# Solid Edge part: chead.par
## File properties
Title: Cross Head
Subject: Carrier Assembly
Author: kiyo
Keywords: Block
Comments: Cross Head
Template: metric.par
Last saved by: edge
Revision: 36
Application: Solid Edge
File Size: 0
Number of Sheets: 0
Number of Objects: 0
Username: kiyo
文書内容のタイプ: 0
Material: チタン, 純金属
Face Style: Steel
Fill Style: ANSI31(Iron)
Virtual Style: 銀
Coef. of Thermal Exp: 0.0
Thermal Conductivity: 16.0
Specific Heat: 519.0
Modulus of Elasticity: 102731879300.0
Poisson's Ratio: 0.34
Yield Stress: 172368925.0
Ultimate Stress: 241316495.0
Elongation: 0.0
Category: Machined Block
Manager: Brian Little
Company: Wheels R Us
Density: 7702
Accuracy: 0.00
Document Number: C-3701
Revision: 1
Project Name: Trolley Wheel Assembly
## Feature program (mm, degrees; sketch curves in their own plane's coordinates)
sketch for "unnamed Protrusion 1" plane through (0, 0, 0) normal (0, -1, 0) x-axis (1, 0, 0)
  line (-53.3125, 21.0114) -> (66.6875, 21.0114)
  line (66.6875, 21.0114) -> (66.6875, -28.9886)
  line (66.6875, -28.9886) -> (-53.3125, -28.9886)
  line (-53.3125, -28.9886) -> (-53.3125, 21.0114)
extrude "unnamed Protrusion 1" add finite 140 along -normal
sketch for "unnamed Hole 1" plane through (6.6875, 0, -3.9886) normal (0, -1, 0) x-axis (1, 0, 0)
  hole centre (30, 0) bore radius 10
hole "unnamed Hole 1" through
sketch for "Hole_2" plane through (6.6875, 0, -3.9886) normal (0, -1, 0) x-axis (1, 0, 0)
  hole centre (-30, 0) bore radius 10
hole "Hole_2" through
pattern "unnamed Pattern 1" of "unnamed Hole 1", "Hole_2"
sketch for "Hole_3" plane through (6.6875, 70, 21.0114) normal (0, 0, 1) x-axis (1, 0, 0)
  hole centre (0, 0) bore radius 10
hole "Hole_3" through  CounterBoreDepth = 12 mm
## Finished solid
Body 1: solid body, 11 faces, 20 edges, 8 vertices.
  Faces by surface: plane 7, cylinder 4
  Edges by curve: line 12, circle 8
Bounding box of the edges (mm): 120.000 x 140.000 x 50.000, from (-53.3125, 0, -28.9886) to (66.6875, 140, 21.0114).
Cylindrical faces by radius (mm): R10 x3, R18 x1
Planar faces by outward normal: +x 1, +y 1, +z 2, -x 1, -y 1, -z 1
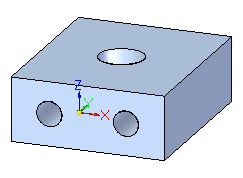
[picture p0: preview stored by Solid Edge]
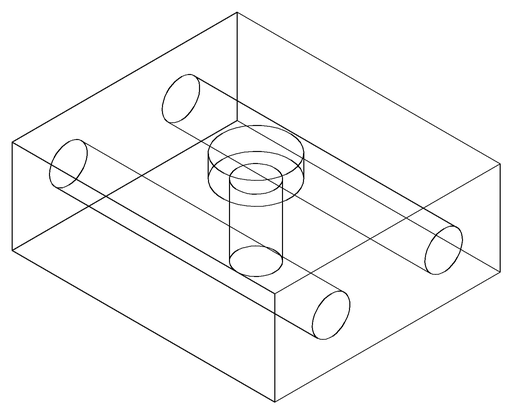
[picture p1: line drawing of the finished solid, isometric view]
